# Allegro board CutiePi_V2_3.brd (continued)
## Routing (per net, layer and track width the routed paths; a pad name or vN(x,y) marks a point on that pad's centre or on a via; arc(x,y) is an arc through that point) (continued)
N12396095: length 4.2
  TOP w0.152: U18.1 58.8,37.7 58.37,38.12 R3039.1 R3040.1
N12403489: length 3.9
  TOP w0.152: R3042.2 59.07,45.07 60.1,44.04 U18.18
N12403491: length 3.6
  TOP w0.152: R3041.2 60.47,44.89 60.75,44.61 U18.17
N12412734: length 2.9
  TOP w0.305: R3051.2 R3049.2 67.53,47.7 U60.4
N12455509: length 4.7
  TOP w0.152: J13.15 6.76,85.75 7.24,86.23 8.26,86.23 9.36,85.13 Q3.3
N12499716: length 1.6
  TOP w0.152: Q5.3 70.81,37.08 D19.2
N12720829: length 7.9
  TOP w0.305: R88.1 R3066.2 R87.2 45.25,15.46 C73.1 45.25,11.61 44.94,11.3 U6.2
N12720893: length 2.6
  TOP w0.305: U6.5 48.69,11.3 C74.1
N12836963: length 2.3
  TOP w0.254: J13.19 6.54,86.55 7.46,87.47 7.46,87.5 R3058.1
N12951060: length 8.9
  TOP w0.127: R122.2 15.31,44.45 15.18,44.58 U5.4 15.18,47.18 14.99,47.37 14.33,47.37 14.1,47.14 14.1,46.61 v1(14.35,46.35)
  BOTTOM w0.127: v1(14.35,46.35) 14.1,46.61 14.1,47.29 13.77,47.62 12.92,47.62 J14.2
N12951086: length 8.9
  TOP w0.127: v1(13.59,46.35) 13.75,46.52 13.75,47.28 14.19,47.71 14.95,47.71 15.18,47.94 U5.3 15.18,49.37 14.99,49.56 14.99,50.35 15.31,50.67 R123.2
  BOTTOM w0.127: J14.3 12.89,47.24 13.63,47.24 13.75,47.12 13.75,46.52 v1(13.59,46.35)
N12951166: length 7
  TOP w0.152: R3086.2 73.03,13.34 72.39,12.7 71.15,12.7 70.87,12.98 R3088.2 70.48,13.34 70.23,13.59 70.23,14.48 69.54,15.17 U597.11
N12951176: length 1.4
  TOP w0.152: R3087.1 59.88,12.83 C2483.2
N12951178: length 3.7
  TOP w0.152: U597.1 65.31,13.49 65.16,13.64 64.85,13.64 64.3,13.08 62.99,13.08 62.74,12.83 R3087.2
N12951240: length 10
  TOP w0.203: U597.18 66.91,17.83 66.84,17.91 66.84,19.43 69.4,22 69.4,23.55 69.2,23.75 R3089.1
N12951278: length 8.8
  TOP w0.152: U597.9 68.94,14.37 69.34,13.97 69.34,12.95 70.1,12.19 70.1,11.84 70.64,11.3 72.52,11.3 73.15,11.94 R3090.2 R3091.1
N12951318: length 38.3
  TOP w0.152: U597.5 66.91,12.37 67.15,12.13
  TOP w0.305: R3094.2 v1(60.36,16.64) ; R3096.2 v1(60.36,15.37) ; C2492.1 69.47,7.75 v1(69.38,7.75) 69.22,7.91 69.22,10.07 67.15,12.13 ; R3102.1 v1(69.88,20.48)
  L03 w0.305: v1(69.88,20.48) 68.1,20.48 65.66,18.03 61.76,18.03 v1(60.36,16.64) v1(60.36,15.37) 60.36,14.19 63.25,11.3 68.58,11.3 69.38,10.51 v1(69.38,7.75)
N12951326: length 8
  TOP w0.152: D20.2 59.18,17.4 62.99,17.4 64.02,16.37 U597.23
N12951328: length 2
  TOP w0.381: D20.1 R3095.1
N12951350: length 4
  TOP w0.152: U597.10 69.18,14.77 69.72,14.22 69.72,13.21 R3097.1
N12951358: length 6.7
  TOP w0.203: U597.12 70.69,15.57 R3101.2 R3103.2 72.49,15.65 73.28,14.86 R3137.2 R3098.2
N12951362: length 7.5
  TOP w0.305: R3098.1 75.18,16.13 77.22,14.1 TP47.1 J23.2
N12951368: length 3.4
  TOP w0.152: R3099.2 62.04,14.41 62.74,15.11 63.91,15.11 63.97,15.17 U597.26
N12951370: length 6.5
  TOP w0.152: D21.2 60.32,18.03 63.12,18.03 64.06,17.09 65.14,17.09 U597.22
N12951372: length 2
  TOP w0.381: D21.1 R3100.1
N12951392: length 6.3
  TOP w0.152: U597.16 67.71,18.31 67.88,18.47 67.88,18.87 68.66,19.66 R3102.2 R3104.2
N12951398: length 4.4
  TOP w0.152: C2493.1 70.77,10.54 69.47,11.84 69.47,12.06 68.71,12.83 68.31,12.83 68.11,13.03 U597.8
N12951408: length 7.2
  TOP w0.152: R3105.2 69.76,8.86 69.76,10.29 67.31,12.74 U597.6
N12951410: length 2.5
  TOP w0.152: R3106.2 69.82,15.97 U597.13
N12951412: length 3.2
  TOP w0.152: R3107.2 70.74,17.88 69.23,16.37 U597.14
N12951420: length 1.9
  TOP w0.152: R3108.1 R3105.1
N12951470: length 6.6
  L03 w0.508: v1(8.38,64.77) v1(7.87,65.28) 6.99,66.17 6.99,69.5 v1(7.87,70.39)
N12951488: length 5.4
  TOP w0.152: J2.A5 8.4,69.24 9.4,70.24 9.4,71.63 9.82,72.05 R3133.1
N12951490: length 5
  TOP w0.152: R3134.1 9.61,63.67 9.14,64.14 9.14,65.03 7.93,66.24 J2.B5
N12951536: length 8.7
  TOP w0.152: J16.1 23.69,4.93 23.84,5.08 25.65,5.08 28.57,2.16 R3138.2
N12951538: length 12.2
  TOP w0.152: R3139.2 31.72,2.92 28.7,2.92 26.04,5.59 22.86,5.59 22.59,5.32 J16.2
N12951540: length 11.4
  TOP w0.152: R3140.2 29.08,3.56 26.42,6.22 22.48,6.22 21.49,5.23 J16.3
N12951542: length 15.7
  TOP w0.152: R3141.2 31.72,7.62 28.19,7.62 28.07,7.75 21.84,7.75 19.29,5.19 J16.5
N12951544: length 15.7
  TOP w0.152: R3142.2 28.45,8.26 28.19,8.51 20.45,8.51 17.09,5.15 J16.7
N12951546: length 17
  TOP w0.152: J16.8 15.99,5.07 20.32,9.4 R3143.2
N13080452: length 2.8
  TOP w0.152: R3174.2 34.85,37.29 U3.1
N13080482: length 7.1
  TOP w0.254: U3.35 34.35,27.12 34.8,26.67 35.05,26.67
  TOP w0.381: FB13.1 38.61,26.67 35.05,26.67
N13080512: length 9.5
  TOP w0.254: U3.34 33.85,26.86 34.67,26.04 34.92,26.04
  TOP w0.381: 34.92,26.04 37.75,26.04 38,25.78 C2503.1 38,23.97 C2504.1 FB8.1
N13080672: length 6.2
  TOP w0.254: U3.29 31.35,26.52 31.24,26.42
  TOP w0.381: 31.24,26.42 30.51,25.68 C2502.1 30.51,24.77 30.48,24.73 C2501.1 30.48,22.35 FB9.1
N13097468: length 5
  TOP w0.152: C2507.1 27.43,25.91 27.84,26.31 29.74,26.31 30.35,26.92 U3.27
N13098112: length 4.4
  TOP w0.508: R3158.2 C2508.2 C2509.1 3.76,14.93 U501.1
N13104223: length 3.5
  TOP w0.254: U501.4 C2510.1 5.59,17.31 5.43,17.47 C2524.2
N13115240: length 1.5
  TOP w0.254: D1.1 65.05,81.4 R3.2
N13167489: length 6.5
  TOP w0.152: J2.B8 8.27,69.74 8.89,70.36 8.89,72.1 TP92.1
N13167505: length 7.5
  TOP w0.152: J2.A8 8.07,66.74 9.58,65.23 9.58,64.59 9.78,64.39 12.06,64.39 TP93.1
N13167521: length 11.9
  TOP w0.127: v1(4.8,68.11) 5.02,68.33 5.84,68.33 5.93,68.24 J2.A6 ; R3162.1 10.09,65.36 9.55,65.9 U601.1 9.55,67.53 9.42,67.65 9.23,67.65 9.06,67.48 8.48,67.48 v1(8.24,67.23) 8.08,67.4 7.83,67.4 7.67,67.24 J2.B6
  BOTTOM w0.127: v1(8.24,67.23) 8.03,67.44 6.62,67.44 5.77,68.3 4.99,68.3 v1(4.8,68.11)
N13167621: length 11.9
  TOP w0.127: J2.B7 5.87,68.74 5.8,68.67 5,68.67 v1(4.8,68.87) ; R3161.1 10.09,70.29 9.55,69.75 U601.6 9.55,68.12 9.42,68 9.09,68 8.91,67.82 8.41,67.82 v1(8.24,68) 7.98,67.74 J2.A7
  BOTTOM w0.127: v1(8.24,68) 8.06,67.82 6.73,67.82 5.84,68.71 4.96,68.71 v1(4.8,68.87)
N13191587: length 3
  TOP w0.152: R3149.2 27.91,52.58 U600.9
N13218298: length 4.4
  TOP w0.152: R3175.2 35.69,39.53 35.69,38.86 34.35,37.52 U3.2
N13235636: length 4.2
  TOP w0.152: TP95.1 39.5,33.02 38.49,32.02 U3.42
N13236221: length 4.5
  TOP w0.254: C2513.1 38.73,28.57 38.1,29.21 38.1,29.97 37.55,30.52 U3.39
N13242775: length 1.4
  TOP w0.152: C2516.2 R3185.1
N13242801: length 2.7
  TOP w0.152: R3185.2 35.18,20.35 R3186.1 35.15,18.95 R3184.1
N13245751: length 3
  TOP w0.152: TP97.1 33.65,17.4 R3188.2 C2519.1
N13245789: length 2.7
  TOP w0.152: R3187.2 32.13,20.35 R3189.2 32.16,18.95 R3188.1
N13245825: length 1.4
  TOP w0.152: C2518.2 R3187.1
N13254228: length 5.8
  TOP w0.152: R3190.2 13.81,21.23 13.66,21.08 11.05,21.08 10.8,21.33 C2520.1 R3192.1
N13255610: length 1.2
  TOP w0.152: C2521.2 R3191.1
N13255658: length 6.2
  TOP w0.254: R3192.2 R3191.2 8.6,20.36 C2522.1 6.31,20.36 6.22,20.45 J27.2
N13279315: length 7.6
  TOP w0.152: R3199.2 C2524.1
N13279395: length 2.4
  TOP w0.152: R3200.2 C2521.1
N13284349: length 2.6
  TOP w0.152: U600.1 TP100.1
N13284361: length 2.8
  TOP w0.152: TP101.1 37.59,44.96 U600.2
N123465088: length 2
  TOP w0.152: U57.9 76.02,86.43 76.2,86.61 R373.2
N124996560: length 2.2
  TOP w0.254: R3060.2 70.76,35.43 D19.1
N132243780: length 1.5
  TOP w0.254: R3178.2 25.28,40.03 D22.1
N132252170: length 1.7
  TOP w0.254: R3179.2 D23.1
N1308043429: length 4.1
  TOP w0.152: TP81.1 33.66,25.4 32.35,26.71 U3.31

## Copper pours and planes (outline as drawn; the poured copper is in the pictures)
3V3 on TOP: 65.66,92.33 68.96,92.33 69.09,92.2 69.09,91.19 68.96,91.06 65.66,91.06 65.53,91.19 65.53,92.2
3V3 on TOP: 35.31,8.38 35.18,8.51 33.78,8.51 33.66,8.38 33.66,7.62 33.4,7.37 32.13,7.37 31.88,7.11 31.88,5.84 32,5.71 34.8,5.71 35.31,6.22
3V3 on TOP: 83.95,59.69 83.95,55.24 83.31,54.61 80.77,54.61 80.52,54.86 80.52,56.26 80.55,56.29 80.55,57.53 80.68,57.66 81.95,57.66 82.2,57.91 82.2,59.56 82.46,59.82 83.82,59.82
3V3 on BOTTOM: 82.04,24.89 73.03,15.88 41.27,15.88 35.31,9.91 35.31,8.13 35.05,7.87 33.02,7.87 32.64,8.26 32.64,16.51 32.77,16.64 35.18,16.64 36.83,18.29 38.35,18.29 42.67,22.61 69.6,22.61 74.42,27.43 74.42,44.2 73.53,45.09 73.15,45.09 72.9,45.34 72.9,66.93 63.06,76.77 63.06,88.77 64.96,90.68 64.96,96.71 65.28,97.03 65.28,97.92 65.53,98.17 65.53,99.44 66.04,99.95 70.61,99.95 71.25,99.31 71.25,80.26 82.42,69.09 82.42,27.81 82.04,27.43
5V_IN on TOP (solid shape): 66.61,16.79 67.14,16.26 67.14,14.53 66.63,14.02 66.63,11.65 66.63,11.33 65.82,10.52 65.82,6.54 65.94,6.41 65.94,4.85 66.04,4.75 66.82,4.75 66.9,4.68 66.9,3.37 66.78,3.25 64.24,3.25 64.16,3.34 64.16,10.78 65.12,11.74 65.47,11.74 66.4,12.68 66.4,14.27 66.53,14.4 66.53,16.36 66.4,16.48 66.4,17.68 66.61,17.68
5V_IN on TOP: 71.14,40.51 71.14,40.51 70.87,40.51 70.74,40.39 70.74,40.39 70.74,39.88 70.61,39.75 69.72,39.75 69.6,39.62 69.6,38.48 69.72,38.35 71.88,38.35 78.3,31.94 78.3,29.15 80.9,26.54 82.04,26.54 82.55,26.04 82.55,24.89 82.68,24.77 84.2,24.77 84.33,24.89 84.33,26.67 82.68,28.32 81.66,28.32 80.07,29.91 80.07,32.32 72.53,39.87 72.53,40.25 72.26,40.51
5V_IN on TOP: 15.88,61.98 15.88,58.68 15.62,58.42 12.7,58.42 12.45,58.68 12.45,62.11 12.57,62.23 15.62,62.23
5V_IN on L03: 20.07,1.4 74.93,1.4 85.09,11.56 85.09,26.67 84.84,26.92 82.8,26.92 82.55,26.67 82.55,12.57 72.9,2.92 67.69,2.92 67.31,3.3 67.31,5.46 66.8,5.97 57.91,5.97 56.39,4.45 28.19,4.45 25.53,7.11 22.48,7.11 19.24,10.35 19.24,50.74 15.68,54.29 15.68,73.85 15.49,74.04 14.48,74.04 14.22,73.79 14.22,72.01 13.84,71.63 10.29,71.63 10.16,71.5 10.16,69.85 10.29,69.72 12.57,69.72 12.83,69.47 12.83,52.58 13.46,51.94 13.46,48.39 14.86,46.99 14.86,6.6
GND on TOP: 44.96,43.69 44.7,43.43 41.02,43.43 40.77,43.69 40.77,47.24 40.51,47.5 39.37,47.5 39.24,47.62 39.24,49.15 40.77,50.67 44.7,50.67 44.96,50.42
GND on TOP: outline of 318 points within 0.51,0.51 89.5,114.49 ; 14 cut-outs
GND on TOP: 21.97,48.64 24.38,48.64 24.51,48.51 24.51,44.96 24.38,44.83 22.1,44.83 21.84,45.09 21.84,48.51
GND on TOP: 68.45,95.63 69.22,96.39 69.22,99.57 68.71,100.08 67.44,100.08 67.18,100.33 66.17,100.33 66.04,100.2 66.04,99.82 66.55,99.31 66.55,98.55 66.42,98.42 65.66,98.42 65.41,98.17 65.41,97.03 64.9,96.52 64.9,94.87 65.15,94.61 68.2,94.61 68.45,94.87
GND on TOP: 65.13,14.83 63.05,14.83 62.64,14.43 62.64,13.59 62.72,13.51 64.19,13.51 64.93,14.25 65.13,14.25 65.18,14.3 65.18,14.43 65.13,14.48 64.24,14.48 64.19,14.53 64.19,14.61 64.24,14.66 65.18,14.66 65.18,14.78
GND on L03: 0.61,24.49 0.54,24.52 0.51,24.59 0.51,39.37 0.73,39.91 1.27,40.13 7.91,40.13 9.16,40.65 9.69,41.91 9.69,52.96 9.16,54.22 7.91,54.74 1.27,54.74 0.73,54.96 0.51,55.5 0.51,92.54 1.94,93.42 2.51,95 2.51,104 1.94,105.58 0.51,106.46 0.51,113.73 0.73,114.27 1.27,114.49 29.72,114.49 30.35,114.49 88.74,114.49 89.28,114.27 89.5,113.73 89.5,1.27 89.28,0.73 88.74,0.51 1.27,0.51 0.73,0.73 0.51,1.27 0.51,17.91 0.54,17.98 0.61,18.01 2.01,18.01 2.8,18.34 3.12,19.13 3.12,23.37 2.8,24.16 2.01,24.49 ; 5 cut-outs
GND on L03: 35.18,61.47 39.12,61.47 41.53,59.05 41.53,51.82 50.55,42.8 50.55,6.22 49.78,5.46 36.58,5.46 34.42,7.62 34.42,60.71
GND on L03: 34.54,98.68 51.05,98.68 51.56,98.17 51.56,80.14 51.05,79.63 48.26,79.63 46.74,81.15 46.74,88.27 45.47,89.53 42.29,89.53 41.15,90.68 34.42,90.68 34.04,91.06 34.04,98.17
GND on L04: 49.15,52.32 53.21,52.32 55.5,50.04 55.5,38.99 56.26,38.23 56.26,36.32 55.63,35.69 55.63,19.05 58.42,16.26 58.42,15.11 58.8,14.73 61.09,14.73 61.47,15.11 61.47,23.88 58.29,27.05 58.29,34.16 58.93,34.8 71.12,34.8 73.79,32.13 73.79,16.13 73.53,15.88 70.48,15.88 69.6,14.99 69.6,12.32 69.22,11.94 64.52,11.94 62.23,9.65 56.64,9.65 54.1,12.19 45.72,12.19 43.05,14.86 43.05,17.14 42.29,17.91 41.15,17.91 34.42,24.64 34.42,29.59 34.67,29.84 35.05,29.84 39.88,34.67 44.96,34.67 46.99,36.7 46.99,50.16
GND on L04: outline of 123 points within 0.51,0.51 89.5,114.49 ; 4 cut-outs
GND on L04: 57.15,53.47 77.09,53.47 78.36,54.74 78.36,65.28 78.11,65.53 75.82,65.53 75.18,64.9 75.18,56.13 74.55,55.5 72.64,55.5 72.39,55.75 72.39,63.75 71.25,64.9 71.25,66.17 60.33,77.09 60.33,80.26 59.56,81.03 54.99,81.03 54.61,80.64 54.61,67.31 55.5,66.42 59.05,66.42 60.71,64.77 60.71,60.96 58.67,58.93 55.75,58.93 55.12,58.29 55.12,55.5
GND on L04: 37.34,73.03 44.32,73.03 44.7,72.64 44.7,57.66 40.39,53.34 36.45,53.34 35.69,54.1 35.69,71.37
GND on L04: 77.34,105.03 80.14,105.03 85.22,99.95 85.22,49.28 84.84,48.9 83.31,48.9 83.06,49.15 83.06,69.09 80.64,71.5 80.64,76.45 77.47,79.63 77.47,93.85 75.31,96.01 75.31,103
VBAT on TOP: 82.93,15.88 82.68,15.62 77.23,15.62 73.55,19.3 73.55,20.59 72.8,21.34 72.8,25.37 72.39,25.78 68.07,25.78 67.82,26.04 67.82,28.96 68.07,29.21 75.56,29.21 77.85,26.92 77.85,21.21 78.99,20.07 82.55,20.07 82.93,19.68
VBAT on TOP: 72.14,44.2 72.14,41.91 72,41.78 71.12,41.78 70.61,42.29 69.98,42.29 69.85,42.42 69.85,44.2 70.1,44.45 71.88,44.45
VBAT on BOTTOM: 69.98,44.45 73.41,44.45 73.91,43.94 73.91,27.69 69.34,23.11 57.66,23.11 57.4,23.37 57.4,26.29 57.91,26.8 65.15,26.8 69.09,30.73 69.09,37.59 69.47,37.97 69.47,43.94
VBUS on TOP (solid shape): 66.2,16.43 66.28,16.36 66.28,14.4 66.23,14.35 66.23,12.72 65.7,12.19 65.57,12.19 65.29,11.91 64.75,11.91 63.86,11.01 63.86,3.34 63.76,3.24 61.16,3.24 61.06,3.34 61.06,4.66 61.12,4.72 61.8,4.72 61.95,4.87 61.95,11.44 63.19,12.67 65.67,12.67 66,13 66,14.35 65.95,14.4 65.95,16.38 66,16.43 66,17.68 66.2,17.68
VBUS on TOP: 68.83,92.71 65.66,92.71 65.53,92.84 65.53,93.98 65.66,94.11 68.83,94.11 69.09,93.85 69.09,92.96
VBUS on TOP: 17.65,51.82 17.65,53.47 17.78,53.59 23.37,53.59 27.05,49.91 27.05,48.01 27.18,47.88 31.75,47.88 31.88,47.75 31.88,47.12 31.75,46.99 25.53,46.99 25.4,47.12 25.4,49.02 22.73,51.69 17.78,51.69
VBUS on TOP: 70.99,100.97 68.71,100.97 68.2,101.47 68.2,104.65 68.33,104.78 69.98,104.78 70.1,104.65 70.1,102.23 70.61,101.73 70.99,101.73 71.12,101.6 71.12,101.09
VBUS on TOP: 44.48,11.94 44.61,12.06 44.61,12.95 44.59,12.97 44.59,13.95 44.58,13.97 44.58,14.48 44.2,14.86 42.16,14.86 41.78,15.24 41.78,18.8 43.05,20.07 43.05,25.65 42.93,25.78 41.02,25.78 40.89,25.65 40.89,22.61 38.1,19.81 38.1,17.02 37.72,16.64 29.84,16.64 29.46,16.26 29.46,13.21 29.84,12.83 33.91,12.83 34.54,12.19 37.85,12.19 38.1,11.94
VBUS on TOP: 10.67,84.07 12.06,84.07 12.19,83.95 12.19,82.55 12.7,82.04 15.62,82.04 15.75,81.92 15.75,79.5 15.62,79.38 11.43,79.38 10.54,80.26 10.54,83.95
VBUS on BOTTOM: 24.89,1.4 22.35,3.94 22.35,16.38 22.61,16.64 32.13,16.64 32.26,16.51 32.26,8 32.77,7.49 35.18,7.49 35.69,8 35.69,9.65 41.4,15.37 74.04,15.37 74.8,14.61 74.8,3.17 73.03,1.4
VBUS on L03: 19.68,51.18 19.68,18.8 25.02,13.46 32.26,13.46 33.66,14.86 33.66,67.56 24.38,76.83 24.38,78.11 21.72,80.77 20.95,80.77 20.57,81.15 16,81.15 15.88,81.28 15.88,81.92 15.75,82.04 11.49,82.04 11.17,81.72 11.17,75.92 12.67,74.42 16.64,74.42 17.02,74.04 17.02,72.26 16.26,71.5 16.26,58.29 18.22,56.32 18.22,52.64
VBUS on L04: 11.3,79.38 8.76,81.92 8.76,85.72 8.51,85.98 8.51,89.41 8.76,89.66 8.76,100.71 13.97,105.92 61.98,105.92 62.67,106.62 67.75,106.62 68.45,105.92 71.88,105.92 73.03,104.78 73.03,94.74 72.26,93.98 69.6,93.98 69.34,93.73 69.34,92.96 69.22,92.84 67.18,92.84 66.93,93.09 66.93,94.49 67.69,95.25 67.69,100.97 66.17,102.49 64.9,102.49 63.88,101.47 15.75,101.47 12.7,98.42 12.7,85.22 15.88,82.04 15.88,79.76 15.49,79.38
VBUSA on TOP: 38.99,46.23 40.13,46.23 40.26,46.1 40.26,44.7 40.13,44.58 38.99,44.58 38.86,44.7 38.86,46.1
VBUSA on TOP: 16.13,54.1 15.75,53.72 15.75,51.56 15.49,51.31 15.11,51.31 13.46,49.66 11.18,49.66 10.92,49.91 10.92,52.2 11.18,52.45 12.32,52.45 13.46,53.59 13.46,55.24 14.61,56.39 17.91,56.39 18.16,56.13 18.16,54.23 18.03,54.1
VBUSA on BOTTOM: 15.37,45.09 15.75,44.7 40.13,44.7 40.51,45.09 40.51,49.66 40.13,50.04 20.83,50.04 19.05,51.82 19.05,54.23 19.68,54.86 19.68,71.75 10.92,80.52 10.92,84.96 8.76,87.12 8.76,88.77 8.51,89.03 7.87,89.03 7.75,88.9 7.75,86.36 9.02,85.09 9.02,78.11 16,71.12 16,58.55 14.73,57.28 14.73,48.9 15.37,48.26
VDD_AMP on TOP: 70.9,103.89 75.31,103.89 75.56,103.63 75.56,99.06 76.07,98.55 78.61,98.55 78.74,98.42 78.74,97.66 78.61,97.54 74.68,97.54 74.42,97.79 74.42,101.47 73.79,102.11 70.87,102.11 70.77,102.2 70.77,103.76
CM_1V8 on TOP: 56.01,97.16 56.9,97.16 57.15,97.41 58.55,97.41 58.67,97.28 58.67,96.65 58.55,96.52 56.01,96.52 55.88,96.65 55.88,97.03
CM_1V8 on L03: 56.9,96.52 63.12,96.52 66.17,99.57 71.88,99.57 74.42,102.11 74.42,106.17 74.8,106.55 79.25,106.55 79.38,106.43 79.38,105.92 79.63,105.66 81.53,105.66 81.66,105.79 81.66,108.33 80.9,109.09 73.79,109.09 70.36,105.66 70.36,104.52 69.85,104.01 66.17,104.01 60.2,98.04 57.15,98.04 56.64,97.54 56.64,96.77
CM_1V8 on L04: 88.77,40.51 89.03,40.77 89.28,40.77 89.41,40.89 89.41,41.4 89.28,41.53 88.77,41.53 88.39,41.91 88.39,101.85 82.3,107.95 79.63,107.95 79.5,107.82 79.5,105.79 79.76,105.54 80.26,105.54 85.6,100.2 85.6,45.59 82.68,42.67 82.68,39.88 82.93,39.62 84.96,39.62 85.85,40.51
CM_3V3 on TOP: 84.84,73.66 84.84,72.52 84.58,72.26 82.93,72.26 82.46,72.74 82.46,73.31 82.93,73.79 84.71,73.79
CM_3V3 on TOP: 15.49,87.5 15.62,87.38 15.62,85.22 14.99,84.58 13.08,84.58 12.95,84.71 12.95,85.6 13.84,86.49 13.84,87.38 13.97,87.5
CM_3V3 on TOP: 58.55,96.27 58.67,96.14 58.67,95.63 58.55,95.5 57.15,95.5 56.9,95.76 55.75,95.76 55.37,95.38 53.72,95.38 53.59,95.5 53.59,96.14 53.72,96.27
CM_3V3 on TOP: 64.9,90.17 64.77,90.04 64.14,90.04 63.75,90.42 61.98,90.42 61.85,90.55 61.85,91.44 61.98,91.57 63.12,92.33 64.77,92.33 64.9,92.2
CM_3V3 on BOTTOM: 83.06,69.22 83.06,41.15 83.31,40.89 85.72,40.89 85.98,41.15 85.98,42.8 86.36,43.18 87.63,43.18 88.01,43.56 88.01,101.73 81.28,108.46 73.91,108.46 71.31,105.85 61.15,105.85 53.34,98.04 53.34,90.55 53.72,90.17 63.88,90.17 64.26,90.55 64.26,97.54 65.15,98.42 65.15,99.69 65.79,100.33 70.74,100.33 71.63,99.44 71.63,88.65 72.14,88.14 72.14,85.09 71.63,84.58 71.63,80.64
CM_3V3 on L04: 53.09,95 54.1,95 54.36,94.74 54.36,94.11 54.74,93.73 61.59,93.73 62.61,92.71 62.61,91.82 61.98,91.19 61.98,90.68 63.63,89.03 63.63,85.09 65.53,83.19 67.56,83.19 67.82,83.44 67.82,85.47 67.56,85.72 66.93,85.72 66.67,85.47 66.67,84.45 66.55,84.33 65.79,84.33 64.64,85.47 64.64,95.38 59.12,100.9 16.19,100.9 13.72,98.42 13.72,85.85 14.48,85.09 15.49,85.09 15.62,85.22 15.62,87.76 15.24,88.14 15.24,94.87 15.75,95.38 17.14,95.38 18.16,96.39 22.23,96.39 22.61,96.77 28.07,96.77 29.84,98.55 49.53,98.55
CM_5V on TOP: 59.05,96.65 62.99,96.65 63.25,96.39 63.25,94.87 63.5,94.61 64.64,94.61 64.77,94.49 64.77,93.09 64.64,92.96 61.85,92.96 60.2,94.61 59.05,94.61 58.93,94.74 58.93,96.52
MCU_3V3 on TOP: 68.22,44.83 61.87,44.83 61.86,44.84 61.33,44.84 61.21,44.96 61.21,46.23 61.34,46.35 61.86,46.35 61.87,46.35 62.73,46.35 62.99,46.61 65.91,46.61 65.92,46.62 66.31,46.22 68.22,46.22 68.34,46.1 68.34,44.95
MCU_3V3 on TOP: 7.24,101.35 8.38,101.35 8.51,101.22 8.51,100.08 8.38,99.95 7.24,99.95 7.11,100.08 7.11,101.22
MCU_3V3 on BOTTOM: 43.69,99.19 45.21,97.66 45.21,81.53 61.59,65.15 61.59,55.24 58.93,52.58 47.88,52.58 47.24,51.94 47.24,32.77 48.26,31.75 67.56,31.75 68.45,32.64 68.45,44.07 69.47,45.09 72.01,45.09 72.26,45.34 72.26,66.8 58.93,80.14 58.17,80.14 55.63,82.68 54.99,82.68 51.56,86.11 51.56,97.66 47.75,101.47 7.87,101.47 7.62,101.22 7.62,99.57 8,99.19
REG3V3 on BOTTOM: 36.58,42.16 37.59,41.15 42.55,41.15 43.56,40.13 43.56,31.62 42.67,30.73 37.97,30.73 35.81,28.57 35.81,22.61 34.16,20.95 22.73,20.95 21.34,22.35 21.34,40.89 22.61,42.16
VD33 on TOP: 25.78,46.61 31.62,46.61 31.75,46.48 31.75,45.97 31.62,45.85 27.3,45.85 27.05,45.59 27.05,45.21 26.8,44.96 25.65,44.96 25.53,45.09 25.53,46.35
VLED+ on TOP: 86.36,33.27 88.65,33.27 88.65,32.26 87.16,32.26 84.74,29.84 81.69,29.84 81.57,29.97 81.57,31.88 81.69,32 84.2,32 85.09,32.89 85.98,32.89
VLED+ on TOP: 43.56,5.33 51.44,5.33 51.69,5.59 51.69,6.35 51.82,6.48 54.23,6.48 54.36,6.35 54.36,3.65 53.75,3.05 43.56,3.05 43.43,3.17 43.43,5.21
VLED+ on L03: 56.39,24.77 56.39,11.18 55.12,9.91 51.94,9.91 51.56,9.53 51.56,5.08 51.82,4.83 56.13,4.83 57.66,6.35 59.56,6.35 59.94,6.73 59.94,20.07 66.47,26.59 81.84,26.59 82.55,27.3 85,27.3 85.12,27.43 85.12,30.32 84.96,30.48 62.1,30.48
VLED- on TOP: 49.44,13.21 53.25,13.21 53.63,13.59 55.28,13.59 55.41,13.46 55.41,11.81 55.28,11.68 52.48,11.68 52.1,12.06 49.44,12.06 49.31,12.19 49.31,13.08
VLED- on TOP: 87.76,34.42 88.65,34.42 88.65,33.53 86.23,33.53 85.98,33.78 84.84,33.78 84.84,33.02 84.07,32.26 81.69,32.26 81.57,32.38 81.57,34.29 81.69,34.42 83.87,34.42 84.12,34.16 87.5,34.16
VLED- on L03: 51.82,26.51 54.75,29.45 54.75,32.91 55.63,33.78 59.07,33.78 59.83,34.54 66.93,34.54 67.82,33.66 71.63,33.66 72.39,32.89 84.11,32.89 84.23,32.77 84.23,30.99 84.11,30.86 61.5,30.86 55.75,25.11 55.75,11.68 55.5,11.43 51.94,11.43 51.82,11.56
N12412618 on TOP: 73.66,39.75 73.66,39.75 73.41,40.01 73.41,43.81 72.14,45.08 69.61,45.08 69.36,45.33 69.36,45.97 69.49,46.1 72.91,46.1 73.17,46.35 73.17,47.24 73.04,47.37 69.61,47.37 69.49,47.49 69.49,48.89 69.61,49.02 74.06,49.02 75.18,47.89 75.18,40.01 74.93,39.75
N12720539 on TOP: 38.51,10.54 44.48,10.54 44.61,10.41 44.61,7.24 44.48,7.11 38.64,7.11 38.39,7.37 38.39,10.41
N12720857 on TOP: 45.88,11.94 48.93,11.94 49.06,12.06 49.06,12.83 48.93,12.95 45.88,12.95 45.75,12.83 45.75,12.06
N12951234 on TOP (solid shape): 66.17,19.83 66.17,18.13 65.82,17.78 65.82,16.56 65.72,16.46 65.72,14.35 65.82,14.25 65.82,13.06 65.59,13.06 65.59,14.05 65.39,14.25 65.39,16.59 65.59,16.79 65.59,17.73 65.41,17.91 65.34,17.91 65.17,18.08 65.17,18.08 64.62,18.63 61.85,18.63 61.78,18.7 61.78,20.39 61.83,20.45 65.55,20.45
N12951240 on TOP: 62.01,22.23 67.47,22.23 67.6,22.35 67.6,25.15 67.47,25.27 62.14,25.27 61.88,25.02 61.88,22.35
N12951470 on TOP: 8.26,70.49 8.26,70.24 8.13,70.11 6.22,70.11 6.1,70.24 6.1,70.49 6.22,70.62 8.13,70.62
N12951470 on TOP: 7.62,65.16 7.49,65.28 6.22,65.28 6.1,65.41 6.1,65.66 6.22,65.79 7.87,65.79 8.76,64.9 8.76,63.76 9.65,62.87 10.54,62.87 10.67,62.74 10.67,60.84 10.54,60.71 8,60.71 7.62,61.09

Small or netless copper shapes (teardrops, artwork), in the pictures only: 1 on TOP, 3 on BOTTOM, 1 on GND02

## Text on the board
DIMENSION: 100 ohm | 90 ohm | 50 ohm | L04 | BOTTOM | 5.0/8.5 | 6.0 | 5.7 | GND02&GND05 | Reflayer | GND02 | GND05
User.28: FIGURE | SIZE | 10.0 | 40.0 | 78.0 | 25.591 | 106.299 | 133.858 | 31.496x23.622 | 47.244x23.622 | 66.929x23.622 | 66.929x25.591 | DRILL CHART: TOP to BOTTOM | ALL UNITS ARE IN MILS | PLATED | NON-PLATED | QTY | 1146 | 4 | 2
